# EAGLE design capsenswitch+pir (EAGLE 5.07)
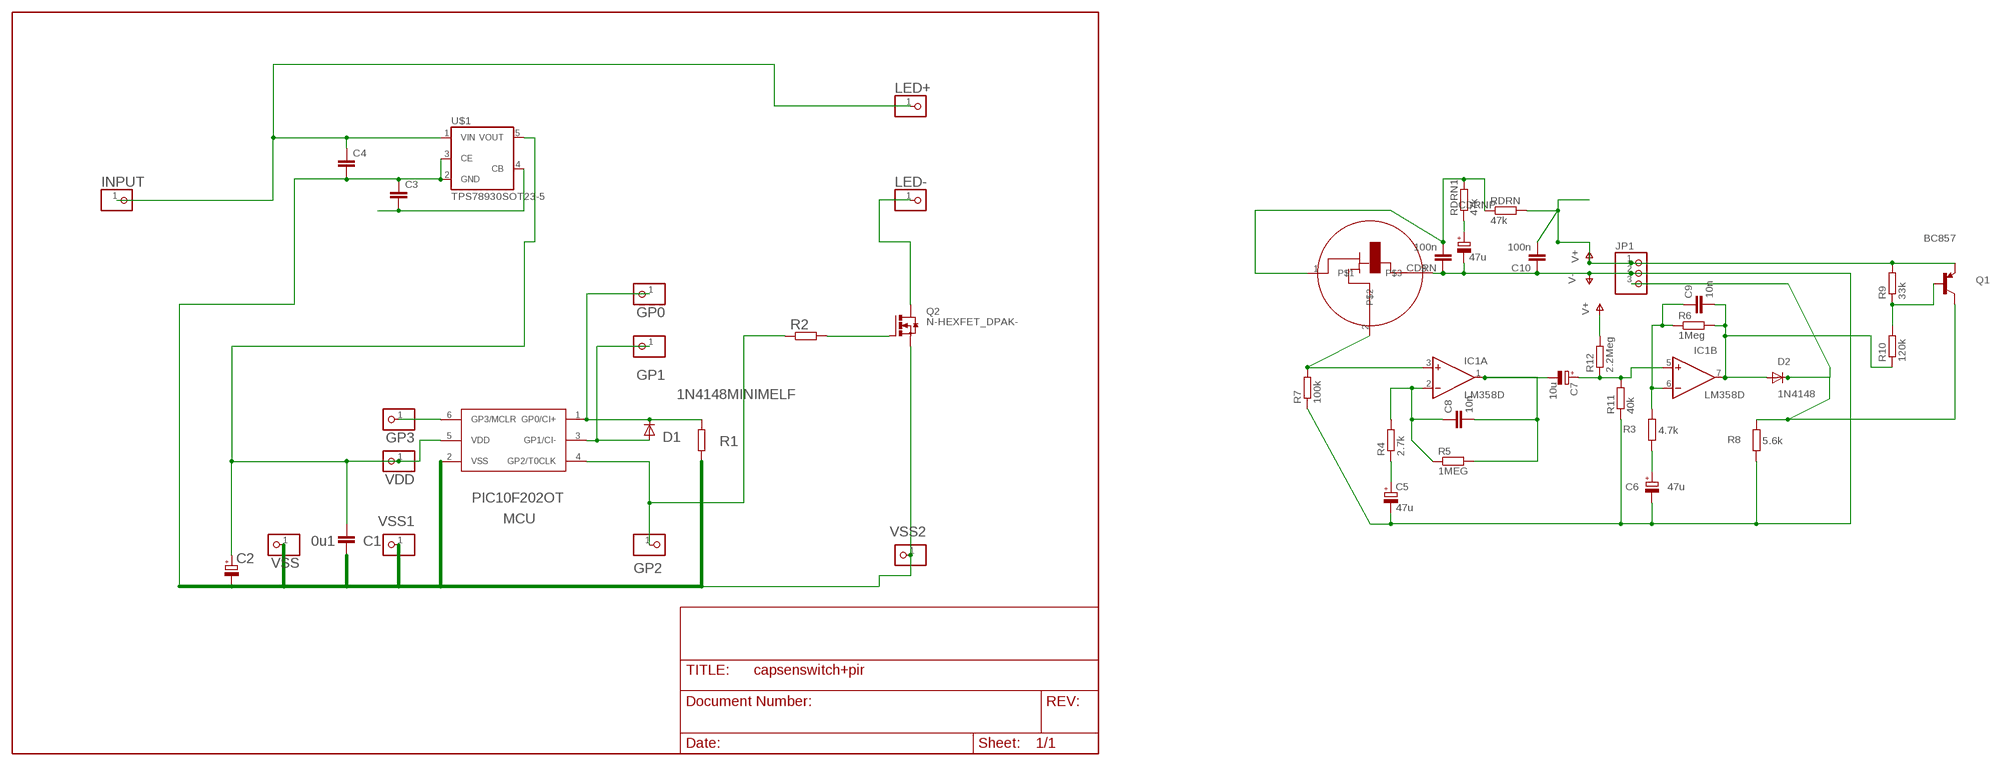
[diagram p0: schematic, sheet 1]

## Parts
C1  0u1  C-EUC1206  [C1206]
C2  CPOL-EUSMCB  [SMC_B]
C3  C-EUC0805  [C0805]
C4  C-EUC1206  [C1206]
C5  47u  CPOL-EUTT2D4L  [TT2D4L]
C6  47u  CPOL-EUTT24LR  [TT24LR]
C7  10u  CPOL-EUTT24LR  [TT24LR]
C8  10n  C-EUC0805  [C0805]
C9  10n  C-EUC0805  [C0805]
C10  100n  C-EUC0805  [C0805]
CDRN  100n  C-EUC0805  [C0805]
CDRNP  47u  CPOL-EUTT2D4L  [TT2D4L]
D1  1N4148MINIMELF  [MINIMELF]
D2  1N4148  1N4148MINIMELF  [MINIMELF]
GP0  PINHD-1X1  [1X01]
GP1  PINHD-1X1  [1X01]
GP2  PINHD-1X1  [1X01]
GP3  PINHD-1X1  [1X01]
IC1  LM358D  [SO08]
INPUT  PINHD-1X1  [1X01]
JP1  PINHD-1X3  [1X03]
LED+  PINHD-1X1  [1X01]
LED-  PINHD-1X1  [1X01]
MCU  PIC10F202OT  [SOT23-6]
PIR  RE200B  [R200B]
Q1  BC857  BC857ALT1SMD  [SOT23-BEC]
Q2  N-HEXFET_DPAK-  [TO252]
R1  R-EU_R0805  [R0805]
R2  R-EU_R0805  [R0805]
R3  4.7k  R-EU_R0805  [R0805]
R4  2.7k  R-EU_R1206  [R1206]
R5  1MEG  R-EU_R0805  [R0805]
R6  1Meg  R-EU_R0805  [R0805]
R7  100k  R-EU_R0805  [R0805]
R8  5.6k  R-EU_R0805  [R0805]
R9  33k  R-EU_R0805  [R0805]
R10  120k  R-EU_R1206  [R1206]
R11  40k  R-EU_R0805  [R0805]
R12  2.2Meg  R-EU_R0805  [R0805]
RDRN  47k  R-EU_R0805  [R0805]
RDRN1  47k  R-EU_R0805  [R0805]
U$1  TPS78930SOT23-5  [SOT25]
VDD  PINHD-1X1  [1X01]
VSS  PINHD-1X1  [1X01]
VSS1  PINHD-1X1  [1X01]
VSS2  PINHD-1X1  [1X01]

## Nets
DRN: CDRN.2 PIR.1 RDRN1.2 RDRN.1
GND: C1.1 C2.- C3.1 C4.2 MCU.2(VSS) Q2.2(S) R1.1 U$1.2(GND) U$1.3(CE) VSS1.1 VSS2.1 VSS.1
GP0: D1.C GP0.1 MCU.1(GP0/CI+) R1.2
GP1: D1.A GP1.1 MCU.3(GP1/CI-)
GP2: GP2.1 MCU.4(GP2/T0CLK) R2.1
GP3: GP3.1 MCU.6(GP3/MCLR)
HOT: LED-.1 Q2.3(D)
N$1: C9.2 D2.A IC1.7(B:OUT) R6.2 R10.1
N$2: CDRNP.+ RDRN1.1
N$3: Q2.1(G) R2.2
N$4: IC1.3(A:+IN) PIR.2 R7.2
N$5: C8.1 IC1.2(A:-IN) R4.2 R5.1
N$6: C5.+ R4.1
N$7: C7.- C8.2 IC1.1(A:OUT) R5.2
N$8: C7.+ IC1.5(B:+IN) R11.2 R12.1
N$9: C9.1 IC1.6(B:-IN) R3.2 R6.1
N$10: C6.+ R3.1
N$11: C3.2 U$1.4(CB)
N$12: Q1.B R9.1 R10.2
SIGNAL: D2.C JP1.3 Q1.C R8.2
V5: C4.1 INPUT.1 LED+.1 U$1.1(VIN)
V+: C10.2 JP1.1 Q1.E R9.2 R12.2 RDRN.2
V-: C5.- C6.- C10.1 CDRN.1 CDRNP.- JP1.2 PIR.3 R7.1 R8.1 R11.1
VDD1: C1.2 C2.+ MCU.5(VDD) U$1.5(VOUT) VDD.1

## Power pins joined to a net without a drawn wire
V+: IC1.8(P:V+)
V-: IC1.4(P:V-)

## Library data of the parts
C1 C3 C4 C8-C10 CDRN = rcl:C-EU: CAPACITOR, European symbol
C2 = rcl-2:CPOL-EU: POLARIZED CAPACITOR, European symbol
C5-C7 CDRNP = rcl:CPOL-EU: POLARIZED CAPACITOR, European symbol
D1 D2 = diode-1:1N4148: DIODE
GP0 GP1-GP3 INPUT LED+ LED- VDD VSS VSS1 VSS2 = pinhead(2):PINHD-1X1: PIN HEADER
IC1 = linear:LM358: OP AMP also LM158; LM258; LM2904 Source: http://cache.national.com/ds/LM/LM158.pdf
JP1 = pinhead:PINHD-1X3: PIN HEADER
MCU = microchip-3:PIC10F2*: uPC nW 0,25/0,5k Program Flash memory Comparator
PIR = photo-elements:RE200B
Q1 = transistor-pnp:BC857*: PNP Transistror
Q2 = transistor-power:N-HEXFET_?-*: HEXFET® Power MOSFET
R1 R2 = rcl-2:R-EU_: RESISTOR, European symbol
R3-R12 RDRN RDRN1 = rcl:R-EU_: RESISTOR, European symbol
U$1 = v-reg:TPS78930

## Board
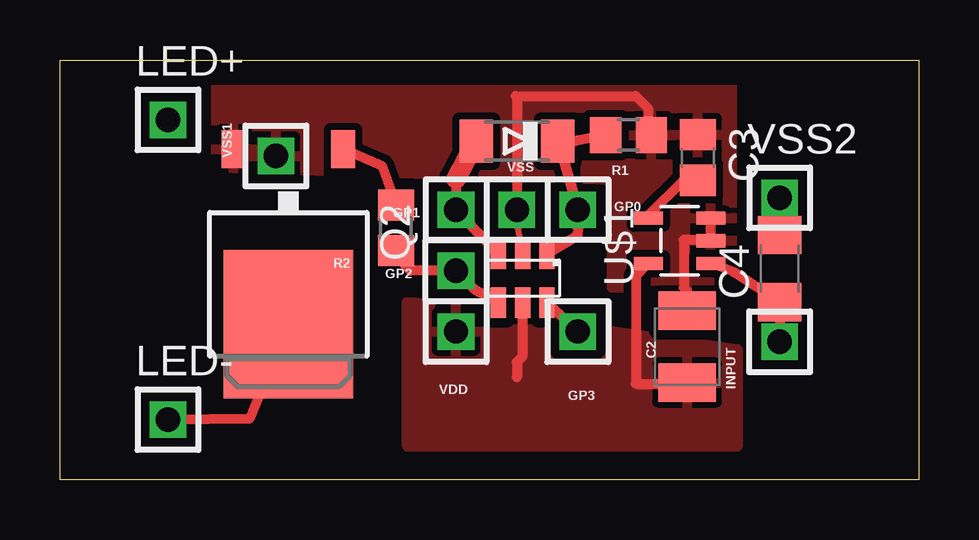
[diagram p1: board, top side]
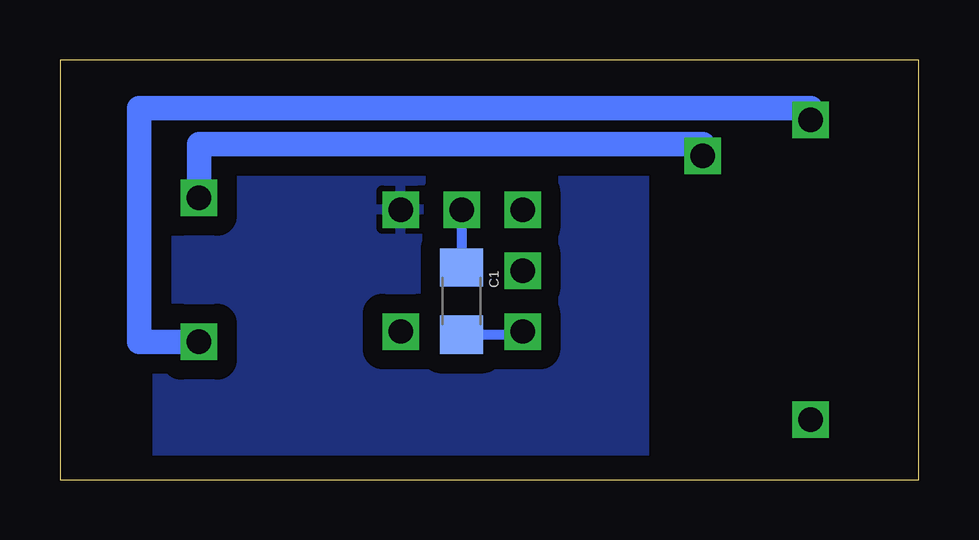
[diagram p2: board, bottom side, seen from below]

Size 35.8 x 17.5 mm. Coordinates in mm from the lower left corner, seen from the top.
Outline: 0,0 0,17.5 35.8,17.5 35.8,0 0,0
Copper layers (1*16): Top 0.035mm / dielectric 1.5mm / Bottom 0.035mm
Design rules "default": minimum track width 10mil, minimum drill 24mil, track to track 8mil, track to pad 8mil, pad to pad 8mil, via to via 8mil, smd to smd 8mil, copper to edge 40mil, drill to drill 8mil, minimum pad ring 10mil, minimum via ring 8mil, stop-mask expansion 4mil, vias tented up to drill 0mil, thermal gap 10mil

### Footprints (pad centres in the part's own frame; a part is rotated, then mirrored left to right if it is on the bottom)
C1206 = smd 1.6 x 1.8: 1 -1.4,0; 2 1.4,0
SMC_B = smd 1.6 x 2.4: + -1.5,0; - 1.5,0
C0805 = smd 1.3 x 1.5: 1 -0.95,0; 2 0.95,0
TT2D4L = drill 0.813 pad 1.6 round: + -1.27,0 | drill 0.813 pad 1.6 octagon: - 1.27,0
TT24LR = drill 0.813 pad 1.6 round: + -1.27,0 | drill 0.813 pad 1.6 octagon: - 1.27,0
MINIMELF = smd 1.4 x 1.8: A 1.7,0; C -1.7,0
1X01 = drill 1.016 square: 1 0,0
SO08 = smd 0.6 x 2.2: 1 -1.905,-2.6; 2 -0.635,-2.6; 3 0.635,-2.6; 4 1.905,-2.6; 5 1.905,2.6; 6 0.635,2.6; 7 -0.635,2.6; 8 -1.905,2.6
1X03 = drill 1.016 long: 1 -2.54,0; 2 0,0; 3 2.54,0
SOT23-6 = smd 0.635 x 1.27: 1 -1.016,-1.016; 2 0,-1.016; 3 1.016,-1.016; 4 1.016,1.016; 5 0,1.016; 6 -1.016,1.016
R200B = drill 0.7 pad 1.4 round: 1 -2.5,0; 2 0,-2.58; 3 2.5,0
SOT23-BEC = smd 1 x 1.4: B -0.95,-1.1; C 0,1.1; E 0.95,-1.1
TO252 = smd 1 x 1.6: 1 -2.28,-3.53; 2 2.28,-3.53 | smd 5.4 x 6.2: 3 0,3.77
R0805 = smd 1.3 x 1.5: 1 -0.95,0; 2 0.95,0
R1206 = smd 1.6 x 1.803: 1 -1.422,0; 2 1.422,0
SOT25 = smd 0.55 x 1.2: 1 -0.95,-1.3; 2 0,-1.3; 3 0.95,-1.3; 4 0.95,1.3; 5 -0.95,1.3

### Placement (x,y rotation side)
C1  19.05,7.45 270 bottom
C2  26.15,5.54 90 top
C3  26.59,13.43 270 top
C4  30,8.8 90 top
C5  not placed on the board
C6  not placed on the board
C7  not placed on the board
C8  not placed on the board
C9  not placed on the board
C10  not placed on the board
CDRN  not placed on the board
CDRNP  not placed on the board
D1  19.05,14.11 180 top
D2  not placed on the board
GP0  21.59,11.26 0 top
GP1  16.51,11.26 0 top
GP2  16.51,8.71 90 top
GP3  21.59,6.17 0 top
IC1  not placed on the board
INPUT  30,5.75 90 top
JP1  not placed on the board
LED+  4.5,15 0 top
LED-  4.5,2.5 0 top
MCU  19.29,8.4 180 top
PIR  not placed on the board
Q1  not placed on the board
Q2  9.52,10.25 180 top
R1  23.7,14.37 180 top
R2  14,10.5 90 top
R3  not placed on the board
R4  not placed on the board
R5  not placed on the board
R6  not placed on the board
R7  not placed on the board
R8  not placed on the board
R9  not placed on the board
R10  not placed on the board
R11  not placed on the board
R12  not placed on the board
RDRN  not placed on the board
RDRN1  not placed on the board
U$1  25.83,9.96 90 top
VDD  16.51,6.17 0 top
VSS  19.05,11.26 0 top
VSS1  9,13.5 90 top
VSS2  30,11.75 0 top

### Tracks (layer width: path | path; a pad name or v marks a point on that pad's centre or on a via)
DRN  (3 unrouted)
GND
  Top 0.254: MCU.2 19.05,10.62 VSS.1
  Top 0.406: U$1.3 U$1.2 27.09,10 26,10 26,8 26.15,7.85 C2.- | C4.2 VSS2.1 | VSS.1 19.05,15.95 19,16 24,16 24.5,15.5 24.5,14.52 R1.1
  Bottom 0.406: VSS.1 C1.1
  Bottom 1.016: VSS2.1 30,14 9,14 VSS1.1
  pour Top (isolate 0.305, rank 2): 6.5,13 6.5,16.5 28,16.5 28,8 23,8 23,12.5
GP0
  Top 0.406: MCU.1 21.57,10.15 21.59,10.48 GP0.1 D1.C 21.46,14.11 R1.2
  pour Bottom (isolate 0.813): 11.43,17.14 31.75,17.14 31.75,-0.64 11.43,-0.64
GP1
  Top 0.406: MCU.3 GP1.1 16.51,12.53
  Top 0.813: D1.A 16.51,12.53
GP2
  Top 0.406: MCU.4 17.29,7.93 GP2.1 14.61,8.71 13.97,9.35 R2.1
GP3
  Top 0.406: GP3.1 MCU.6
HOT
  Top 0.406: LED-.1 7.9,2.54 Q2.3
N$1  (4 unrouted)
N$2  (1 unrouted)
N$3
  Top 0.406: R2.2 13.42,13.08 Q2.1
N$4  (2 unrouted)
N$5  (3 unrouted)
N$6  (1 unrouted)
N$7  (3 unrouted)
N$8  (3 unrouted)
N$9  (3 unrouted)
N$10  (1 unrouted)
N$11
  Top 0.406: U$1.4 24.53,11.03 26,12.5 26.58,12.5 C3.2
N$12  (2 unrouted)
SIGNAL  (3 unrouted)
V5
  Top 0.406: U$1.1 28.09,8.65 C4.1 INPUT.1
  Bottom 1.016: INPUT.1 32.5,5.75 32.5,15.5 4.5,15.5 LED+.1
V+  (6 unrouted)
V-  (10 unrouted)
VDD1
  Top 0.406: MCU.5 19.27,5.13 19.05,4.91 19.05,4.27 | U$1.5 24.51,9.01 24,8.5 24,4 26.11,4 C2.+
  Bottom 0.406: C1.2 17.14,6.04 VDD.1
  pour Top (isolate 0.406): 14.47,7.45 28.25,5.45 28.25,1.36 14.47,1.36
